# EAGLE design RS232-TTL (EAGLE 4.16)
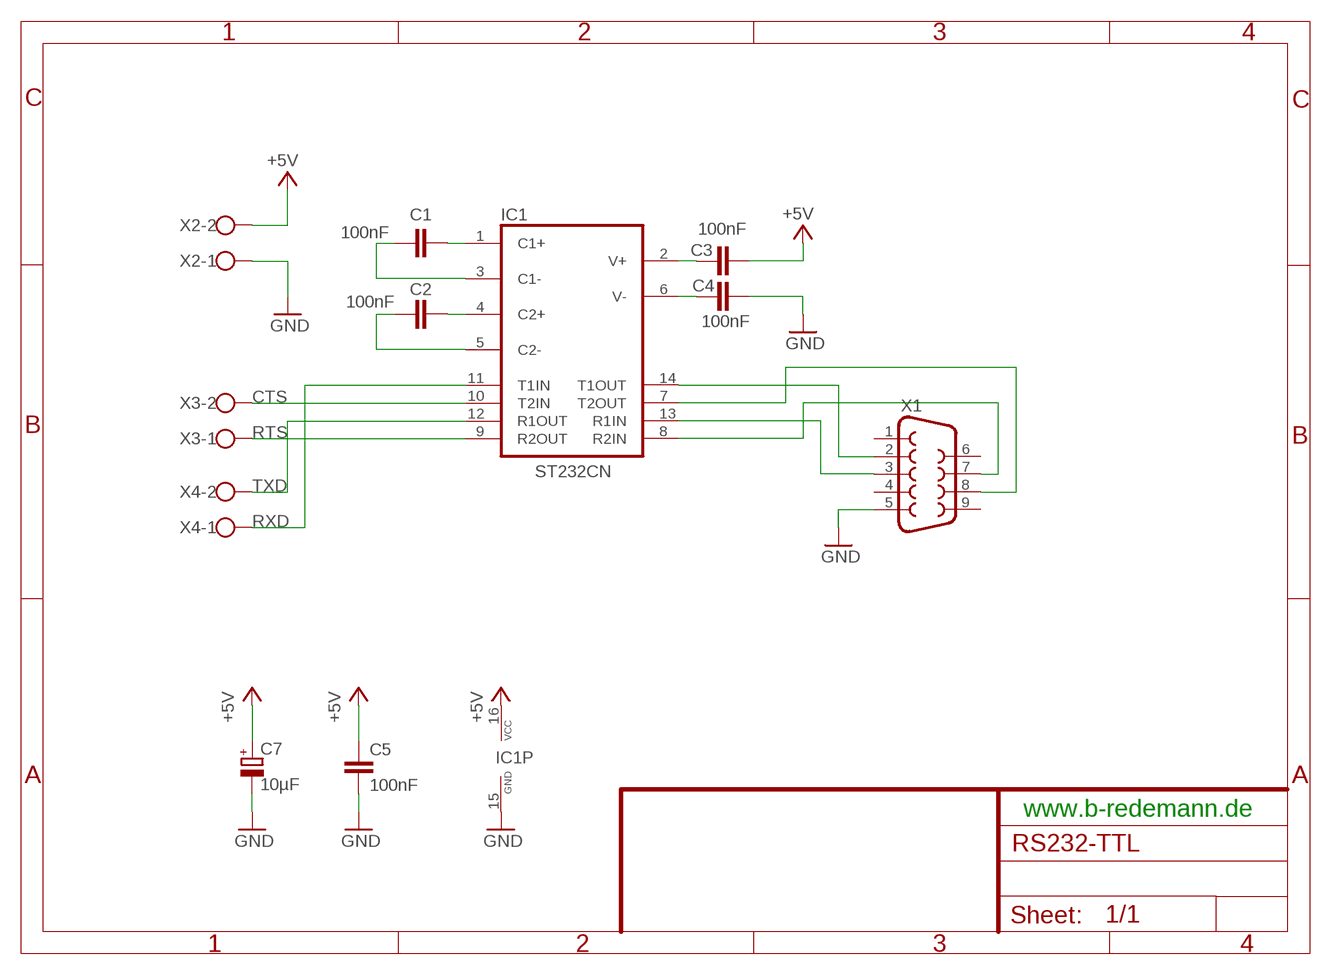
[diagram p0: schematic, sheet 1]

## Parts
C1  100nF  C-EU025-024X044  [C025-024X044]
C2  100nF  C-EU025-024X044  [C025-024X044]
C3  100nF  C-EU025-024X044  [C025-024X044]
C4  100nF  C-EU025-024X044  [C025-024X044]
C5  100nF  C-EU025-024X044  [C025-024X044]
C7  10µF  CPOL-EUE1.8-4  [E1,8-4]
IC1  ST232CN  MAX232  [DIL16]
X1  F09H  [F09H]
X2  W237-02P  [W237-132]
X3  W237-02P  [W237-132]
X4  W237-02P  [W237-132]

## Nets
+5V: C3.2 C5.1 C7.+ IC1.16(VCC) X2.2
CTS: IC1.10(T2IN) X3.2
GND: C4.2 C5.2 C7.- IC1.15(GND) X1.5 X2.1
N$1: C1.2 IC1.1(C1+)
N$2: C2.2 IC1.4(C2+)
N$3: C1.1 IC1.3(C1-)
N$4: C2.1 IC1.5(C2-)
N$5: C3.1 IC1.2(V+)
N$6: C4.1 IC1.6(V-)
N$7: IC1.14(T1OUT) X1.2
N$8: IC1.13(R1IN) X1.3
N$9: IC1.8(R2IN) X1.7
N$10: IC1.7(T2OUT) X1.8
RTS: IC1.9(R2OUT) X3.1
RXD: IC1.11(T1IN) X4.1
TXD: IC1.12(R1OUT) X4.2
Unconnected: X1.1 X1.4 X1.6 X1.9

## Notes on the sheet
- www.b-redemann.de

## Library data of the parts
C1-C5 = BRedemannSpecial:C-EU: CAPACITOR, European symbol
C7 = BRedemannSpecial:CPOL-EU: POLARIZED CAPACITOR, European symbol
IC1 = maxim:MAX232: RS232 TRANSEIVER
X1 = con-subd:F09: SUB-D
X2-X4 = con-wago-508:W237-02P: WAGO SREW CLAMP

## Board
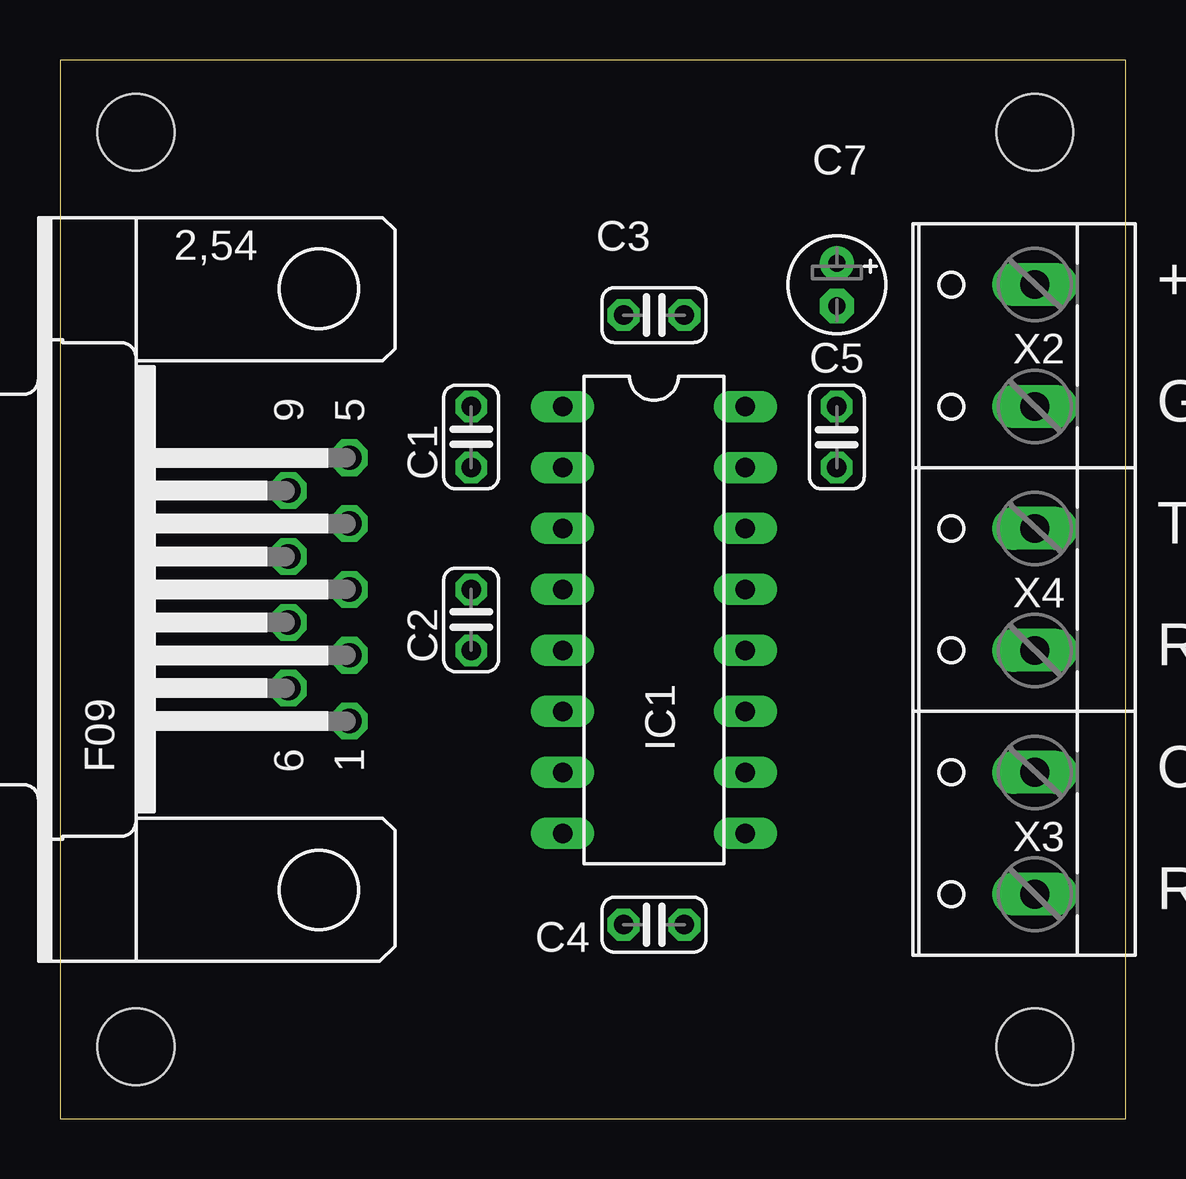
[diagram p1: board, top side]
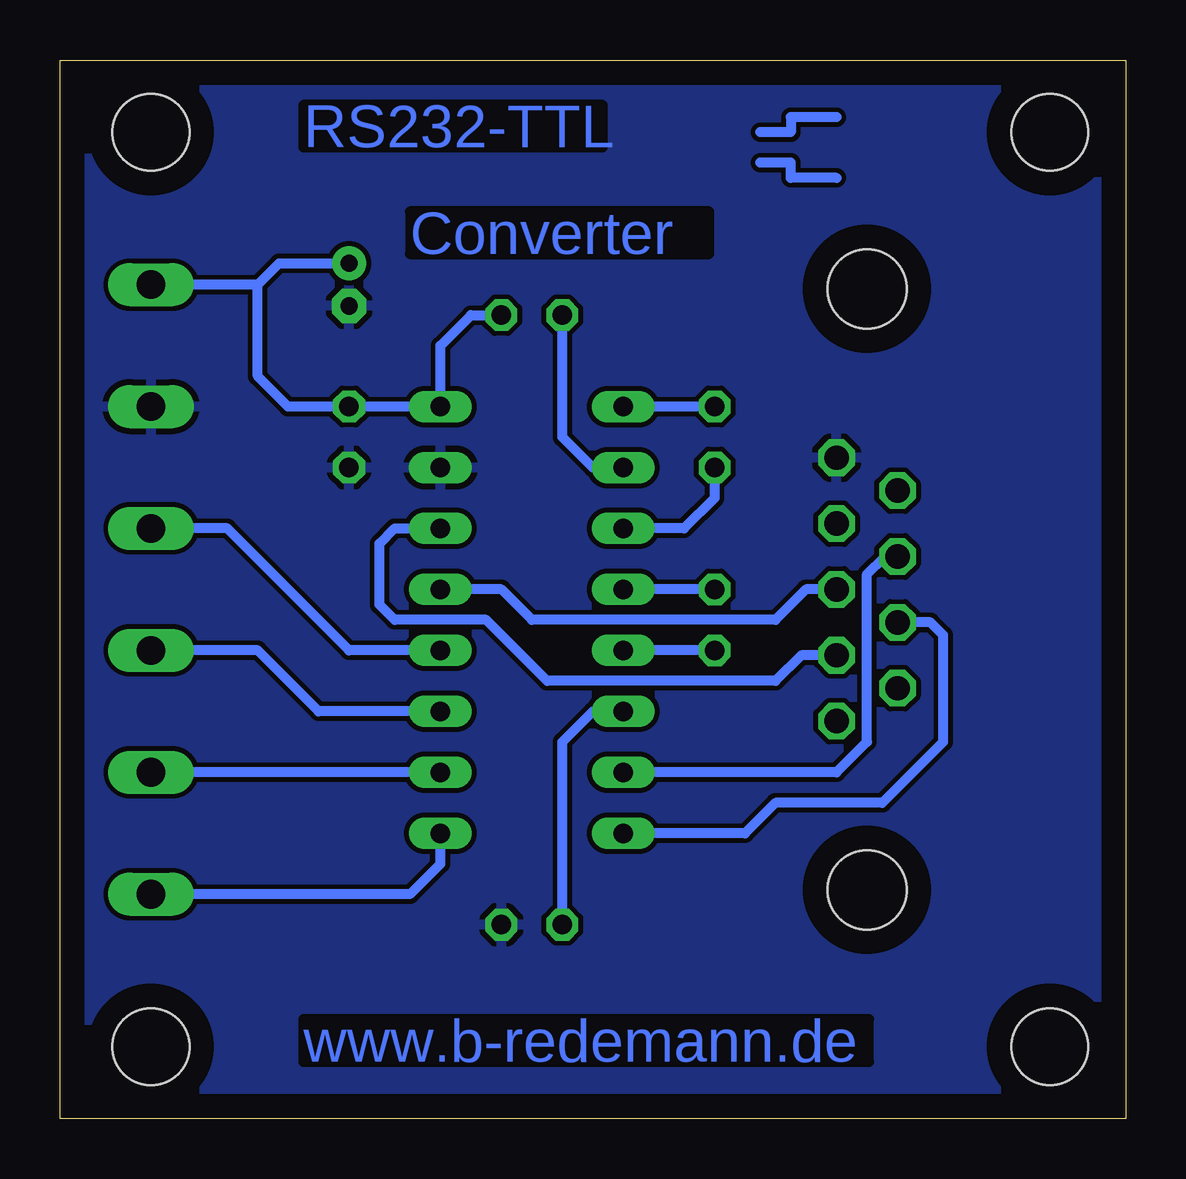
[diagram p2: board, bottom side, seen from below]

Size 44.43 x 44.12 mm. Coordinates in mm from the lower left corner, seen from the top.
Outline: 0,0 44.43,0 44.43,44.12 0,44.12 0,0
Copper layers (1*16): Top 0.035mm / dielectric 1.5mm / Bottom 0.035mm
Design rules "default": minimum track width 10mil, minimum drill 24mil, track to track 8mil, track to pad 8mil, pad to pad 8mil, via to via 8mil, smd to smd 8mil, copper to edge 40mil, drill to drill 8mil, minimum pad ring 10mil, minimum via ring 8mil, stop-mask expansion 4mil, vias tented up to drill 0mil, thermal gap 10mil
Holes 3.2 mm at 3.17,3.01 3.17,41.11 40.64,41.11 40.64,3.01

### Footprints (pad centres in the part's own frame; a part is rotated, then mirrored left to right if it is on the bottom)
C025-024X044 = drill 0.813 octagon: 1 -1.27,0; 2 1.27,0
E1,8-4 = drill 0.711 pad 1.422 round: + -0.889,0 | drill 0.711 pad 1.422 octagon: - 0.889,0
DIL16 = drill 0.813 long: 1 -8.89,-3.81; 2 -6.35,-3.81; 3 -3.81,-3.81; 4 -1.27,-3.81; 5 1.27,-3.81; 6 3.81,-3.81; 7 6.35,-3.81; 8 8.89,-3.81; 9 8.89,3.81; 10 6.35,3.81; 11 3.81,3.81; 12 1.27,3.81; 13 -1.27,3.81; 14 -3.81,3.81; 15 -6.35,3.81; 16 -8.89,3.81
F09H = drill 1.016 octagon: 1 -5.486,-1.27; 2 -2.743,-1.27; 3 0,-1.27; 4 2.743,-1.27; 5 5.486,-1.27; 6 -4.115,1.27; 7 -1.372,1.27; 8 1.372,1.27; 9 4.115,1.27 | hole 3.302: -12.522,0; 12.522,0
W237-132 = drill 1.194 long: 1 -2.54,-0.635; 2 2.54,-0.635

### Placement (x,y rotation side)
C1  17.14,28.41 90 top
C2  17.14,20.79 90 top
C3  24.76,33.49 0 top
C4  24.76,8.09 0 top
C5  32.38,28.41 270 top
C7  32.38,34.76 270 top
IC1  24.76,20.79 270 top
X1  10.79,22.06 90 top
X2  40,32.22 90 top
X3  40,11.9 90 top
X4  40,22.06 90 top

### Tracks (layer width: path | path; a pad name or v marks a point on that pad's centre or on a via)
+5V
  Bottom 0.406: C7.+ 35.3,35.65 36.19,34.76 | 36.19,34.76 36.19,30.95 34.92,29.68 C5.1 IC1.16 28.57,32.22 27.3,33.49 C3.2 | 36.19,34.76 X2.2
CTS
  Bottom 0.406: IC1.10 X3.2
GND
  pour Bottom: -0.64,43.65 45.08,43.65 45.08,0.47 -0.64,0.47
N$1
  Bottom 0.406: C1.2 IC1.1
N$2
  Bottom 0.406: C2.2 IC1.4
N$3
  Bottom 0.406: IC1.3 18.41,24.6 17.14,25.87 C1.1
N$4
  Bottom 0.406: C2.1 IC1.5
N$5
  Bottom 0.406: C3.1 23.49,28.41 22.22,27.14 IC1.2
N$6
  Bottom 0.406: IC1.6 22.22,16.98 23.49,15.71 C4.1
N$7
  Bottom 0.406: X1.2 13.53,19.32 14.6,18.25 24.12,18.25 26.66,20.79 30.47,20.79 31.11,21.42 31.11,23.96 30.47,24.6 IC1.14
N$8
  Bottom 0.406: IC1.13 26.03,22.06 24.76,20.79 14.6,20.79 13.33,22.06 X1.3
N$9
  Bottom 0.406: X1.7 8.15,20.69 7.62,20.15 7.62,15.71 10.16,13.17 14.6,13.17 15.87,11.9 IC1.8
N$10
  Bottom 0.406: X1.8 10.05,23.43 10.79,22.7 10.79,15.71 12.06,14.44 IC1.7
N$11
  Bottom 0.406: 12.06,41.74 13.97,41.74 13.97,41.11 15.24,41.11
N$12
  Bottom 0.406: 12.06,39.2 13.97,39.2 13.97,39.84 15.24,39.84
RTS
  Bottom 0.406: IC1.9 28.57,10.63 29.84,9.36 X3.1
RXD
  Bottom 0.406: IC1.11 33.65,16.98 36.19,19.52 X4.1
TXD
  Bottom 0.406: IC1.12 32.38,19.52 37.46,24.6 X4.2

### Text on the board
Bottom: RS232-TTL | Converter | www.b-redemann.de
tPlace: +5V | GND | TxD | RxD | CTS | RTS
